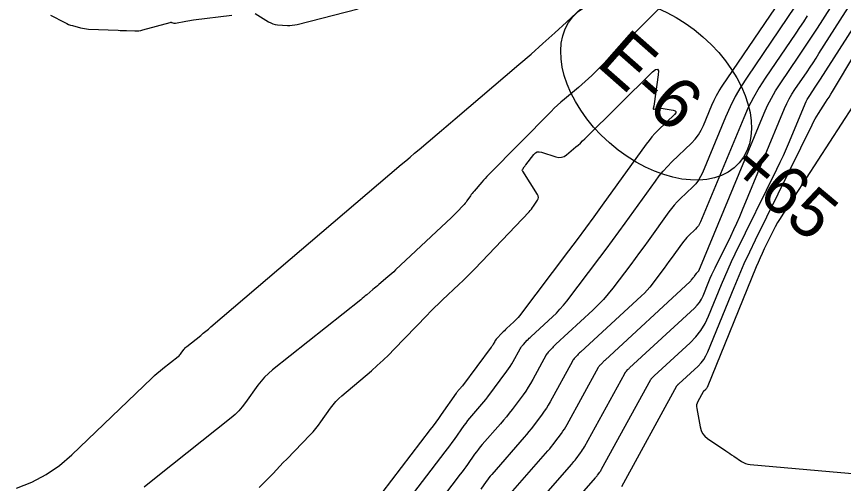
# Model space of a CAD drawing. Extents: x 1005228 to 1008882, y 1883389 to 1885754.
# Drawn here: x 1007760 to 1007862.3, y 1884472.7 to 1884530.4 of the extents above; entities that cross this region are included whole.
import ezdxf

# ---------------------------------------------------------------- set-up
doc = ezdxf.new("R2010")
doc.units = 0
for name, color, linetype in [('C-ANNO-NOTE', 7, 'Continuous'), ('R_Erosion', 7, 'Continuous'), ('S_BASELINE', 7, 'Continuous'), ('S_BRIDGE', 7, 'Continuous')]:
    doc.layers.add(name, color=color, linetype=linetype)

msp = doc.modelspace()

# ---------------------------------------------------------------- linework, layer by layer
at = {"layer": 'C-ANNO-NOTE'}
for points in [[(1007760.01, 1884472.07), (1007761.9, 1884472.81), (1007763.67, 1884473.75), (1007765.33, 1884474.87), (1007766.86, 1884476.2), (1007776.76, 1884485.69), (1007777.08, 1884486), (1007777.42, 1884486.3), (1007777.76, 1884486.59), (1007778.11, 1884486.87), (1007780, 1884488.38), (1007780.1, 1884488.47), (1007780.2, 1884488.56), (1007780.29, 1884488.67), (1007780.37, 1884488.78), (1007780.69, 1884489.22), (1007780.78, 1884489.33), (1007780.87, 1884489.43), (1007780.96, 1884489.53), (1007781.07, 1884489.62), (1007782.78, 1884490.98), (1007783.1, 1884491.24), (1007783.42, 1884491.5), (1007783.73, 1884491.76), (1007784.05, 1884492.03), (1007807.58, 1884512.12), (1007808.14, 1884512.59), (1007808.69, 1884513.06), (1007809.24, 1884513.53), (1007809.8, 1884514), (1007812.02, 1884515.88), (1007812.57, 1884516.35), (1007813.13, 1884516.83), (1007813.68, 1884517.3), (1007814.23, 1884517.77), (1007822.14, 1884524.51), (1007823.63, 1884525.8), (1007825.11, 1884527.11), (1007826.58, 1884528.43), (1007828.03, 1884529.77), (1007845.59, 1884546.16)], [(1007824.7, 1884465.47), (1007831.59, 1884473.36), (1007831.66, 1884473.44), (1007831.73, 1884473.52), (1007831.8, 1884473.61), (1007831.87, 1884473.7), (1007832.13, 1884474.05), (1007832.19, 1884474.13), (1007832.25, 1884474.22), (1007832.31, 1884474.32), (1007832.36, 1884474.41), (1007838.45, 1884485.51), (1007838.47, 1884485.56), (1007838.5, 1884485.6), (1007838.54, 1884485.64), (1007838.57, 1884485.68), (1007838.71, 1884485.83), (1007838.75, 1884485.87), (1007838.78, 1884485.9), (1007838.82, 1884485.94), (1007838.86, 1884485.97), (1007843.31, 1884490.08), (1007844.01, 1884490.81), (1007844.63, 1884491.6), (1007845.16, 1884492.46), (1007845.59, 1884493.38), (1007847.17, 1884497.27), (1007847.58, 1884498.24), (1007847.99, 1884499.19), (1007848.43, 1884500.14), (1007848.88, 1884501.08), (1007854.04, 1884511.56), (1007854.45, 1884512.41), (1007854.84, 1884513.26), (1007855.22, 1884514.12), (1007855.59, 1884514.98), (1007857.52, 1884519.63), (1007857.64, 1884519.91), (1007857.78, 1884520.17), (1007857.93, 1884520.43), (1007858.09, 1884520.69), (1007858.77, 1884521.69), (1007858.94, 1884521.94), (1007859.1, 1884522.19), (1007859.27, 1884522.44), (1007859.43, 1884522.69), (1007868.54, 1884536.99)], [(1007819.94, 1884470.09), (1007825.72, 1884476.7), (1007825.94, 1884476.96), (1007826.16, 1884477.22), (1007826.37, 1884477.49), (1007826.57, 1884477.75), (1007827.38, 1884478.84), (1007827.58, 1884479.11), (1007827.77, 1884479.39), (1007827.94, 1884479.68), (1007828.11, 1884479.97), (1007831.98, 1884487.03), (1007832.03, 1884487.12), (1007832.09, 1884487.2), (1007832.15, 1884487.28), (1007832.22, 1884487.35), (1007832.49, 1884487.64), (1007832.56, 1884487.72), (1007832.63, 1884487.79), (1007832.7, 1884487.86), (1007832.78, 1884487.93), (1007843.29, 1884497.64), (1007843.35, 1884497.69), (1007843.4, 1884497.74), (1007843.44, 1884497.8), (1007843.49, 1884497.85), (1007843.66, 1884498.09), (1007843.71, 1884498.14), (1007843.75, 1884498.2), (1007843.79, 1884498.26), (1007843.84, 1884498.32), (1007844.04, 1884498.6), (1007844.06, 1884498.63), (1007844.09, 1884498.67), (1007844.12, 1884498.7), (1007844.15, 1884498.73), (1007844.27, 1884498.85), (1007844.3, 1884498.88), (1007844.33, 1884498.91), (1007844.35, 1884498.95), (1007844.37, 1884498.99), (1007852.46, 1884518.48), (1007852.88, 1884519.42), (1007853.35, 1884520.35), (1007853.86, 1884521.24), (1007854.42, 1884522.11), (1007856.76, 1884525.55), (1007857.34, 1884526.41), (1007857.91, 1884527.28), (1007858.48, 1884528.14), (1007859.04, 1884529.02), (1007862.55, 1884534.53)], [(1007840.11, 1884532.04), (1007835.26, 1884527.23), (1007834.76, 1884526.75), (1007834.27, 1884526.26), (1007833.78, 1884525.78), (1007833.29, 1884525.29), (1007831.14, 1884523.16), (1007830.73, 1884522.77), (1007830.32, 1884522.39), (1007829.91, 1884522.02), (1007829.48, 1884521.65), (1007827.76, 1884520.22), (1007827.33, 1884519.85), (1007826.92, 1884519.48), (1007826.51, 1884519.09), (1007826.11, 1884518.7), (1007818.36, 1884510.86), (1007818.15, 1884510.64), (1007817.94, 1884510.41), (1007817.74, 1884510.19), (1007817.53, 1884509.96), (1007816.58, 1884508.84), (1007816.46, 1884508.7), (1007816.34, 1884508.55), (1007816.23, 1884508.41), (1007816.13, 1884508.25), (1007815.71, 1884507.64), (1007815.6, 1884507.49), (1007815.49, 1884507.34), (1007815.37, 1884507.2), (1007815.25, 1884507.07), (1007814.48, 1884506.26), (1007814.31, 1884506.08), (1007814.13, 1884505.91), (1007813.96, 1884505.73), (1007813.78, 1884505.56), (1007806.89, 1884499.08), (1007806.65, 1884498.86), (1007806.41, 1884498.65), (1007806.17, 1884498.43), (1007805.92, 1884498.22), (1007804.82, 1884497.28), (1007804.63, 1884497.13), (1007804.44, 1884496.97), (1007804.26, 1884496.81), (1007804.07, 1884496.65), (1007803.33, 1884496.02), (1007803.14, 1884495.86), (1007802.96, 1884495.7), (1007802.77, 1884495.55), (1007802.58, 1884495.4), (1007791.66, 1884486.71), (1007791.16, 1884486.28), (1007790.69, 1884485.83), (1007790.26, 1884485.33), (1007789.86, 1884484.81), (1007788.33, 1884482.66), (1007787.93, 1884482.14), (1007787.5, 1884481.65), (1007787.04, 1884481.19), (1007786.54, 1884480.76), (1007777.47, 1884473.55), (1007775.8, 1884472.19)], [(1007789.53, 1884530.81), (1007791.18, 1884529.8), (1007791.44, 1884529.66), (1007791.72, 1884529.55), (1007792.01, 1884529.48), (1007792.3, 1884529.44), (1007793.51, 1884529.35), (1007793.81, 1884529.35), (1007794.11, 1884529.36), (1007794.41, 1884529.4), (1007794.7, 1884529.46), (1007802.24, 1884531.4)], [(1007807.42, 1884469.23), (1007813.02, 1884476.56), (1007813.31, 1884476.94), (1007813.6, 1884477.32), (1007813.88, 1884477.71), (1007814.15, 1884478.1), (1007815.36, 1884479.82), (1007815.59, 1884480.13), (1007815.82, 1884480.43), (1007816.06, 1884480.73), (1007816.31, 1884481.02), (1007817.31, 1884482.17), (1007817.56, 1884482.46), (1007817.8, 1884482.76), (1007818.04, 1884483.06), (1007818.27, 1884483.36), (1007820.65, 1884486.55), (1007820.86, 1884486.84), (1007821.06, 1884487.13), (1007821.25, 1884487.44), (1007821.42, 1884487.74), (1007822.29, 1884489.32), (1007822.37, 1884489.46), (1007822.47, 1884489.61), (1007822.57, 1884489.74), (1007822.69, 1884489.87), (1007823.16, 1884490.37), (1007823.28, 1884490.49), (1007823.4, 1884490.62), (1007823.53, 1884490.74), (1007823.65, 1884490.85), (1007826.29, 1884493.29), (1007826.76, 1884493.75), (1007827.21, 1884494.22), (1007827.64, 1884494.72), (1007828.05, 1884495.23), (1007832.12, 1884500.61), (1007832.92, 1884501.67), (1007833.71, 1884502.74), (1007834.5, 1884503.81), (1007835.27, 1884504.89), (1007839.01, 1884510.08), (1007839.48, 1884510.71), (1007839.98, 1884511.31), (1007840.5, 1884511.89), (1007841.06, 1884512.45), (1007843.48, 1884514.79), (1007843.93, 1884515.28), (1007844.33, 1884515.81), (1007844.68, 1884516.37), (1007844.96, 1884516.97), (1007846, 1884519.46), (1007846.27, 1884520.08), (1007846.57, 1884520.67), (1007846.91, 1884521.26), (1007847.27, 1884521.82), (1007853.87, 1884531.54)], [(1007856.3, 1884531.71), (1007850.35, 1884522.95), (1007849.59, 1884521.76), (1007848.89, 1884520.53), (1007848.25, 1884519.28), (1007847.67, 1884517.98), (1007844.82, 1884511.12), (1007844.59, 1884510.63), (1007844.32, 1884510.18), (1007844, 1884509.76), (1007843.63, 1884509.37), (1007842.09, 1884507.88), (1007841.71, 1884507.5), (1007841.35, 1884507.1), (1007841.01, 1884506.68), (1007840.68, 1884506.26), (1007838.13, 1884502.7), (1007837.59, 1884501.96), (1007837.06, 1884501.23), (1007836.51, 1884500.5), (1007835.97, 1884499.77), (1007833.74, 1884496.83), (1007833.18, 1884496.11), (1007832.58, 1884495.42), (1007831.95, 1884494.76), (1007831.29, 1884494.12), (1007826.69, 1884489.88), (1007826.59, 1884489.78), (1007826.48, 1884489.67), (1007826.37, 1884489.57), (1007826.27, 1884489.46), (1007825.86, 1884489.03), (1007825.77, 1884488.92), (1007825.68, 1884488.8), (1007825.59, 1884488.68), (1007825.52, 1884488.56), (1007823.86, 1884485.54), (1007823.58, 1884485.04), (1007823.28, 1884484.56), (1007822.97, 1884484.09), (1007822.64, 1884483.63), (1007821.28, 1884481.81), (1007820.93, 1884481.36), (1007820.58, 1884480.92), (1007820.22, 1884480.48), (1007819.85, 1884480.05), (1007817.6, 1884477.47), (1007817.36, 1884477.18), (1007817.12, 1884476.89), (1007816.88, 1884476.58), (1007816.66, 1884476.27), (1007815.78, 1884475.02), (1007815.56, 1884474.71), (1007815.34, 1884474.4), (1007815.11, 1884474.09), (1007814.88, 1884473.79), (1007810.86, 1884468.52)], [(1007764.22, 1884530.63), (1007765.98, 1884529.69), (1007766.21, 1884529.58), (1007766.45, 1884529.48), (1007766.69, 1884529.39), (1007766.93, 1884529.32), (1007767.91, 1884529.05), (1007768.16, 1884528.99), (1007768.41, 1884528.95), (1007768.66, 1884528.91), (1007768.92, 1884528.9), (1007772.56, 1884528.74), (1007772.82, 1884528.73), (1007773.07, 1884528.72), (1007773.33, 1884528.71), (1007773.59, 1884528.7), (1007774.62, 1884528.67), (1007774.88, 1884528.67), (1007775.13, 1884528.69), (1007775.38, 1884528.73), (1007775.63, 1884528.79), (1007779.01, 1884529.72), (1007779.07, 1884529.73), (1007779.12, 1884529.73), (1007779.18, 1884529.72), (1007779.23, 1884529.71), (1007779.45, 1884529.64), (1007779.51, 1884529.62), (1007779.57, 1884529.62), (1007779.62, 1884529.62), (1007779.68, 1884529.62), (1007780.96, 1884529.88), (1007781.19, 1884529.93), (1007781.43, 1884529.97), (1007781.66, 1884530.01), (1007781.9, 1884530.04), (1007786.63, 1884530.63)], [(1007857.79, 1884530.54), (1007857.32, 1884529.81), (1007856.84, 1884529.09), (1007856.36, 1884528.38), (1007852.59, 1884522.83), (1007851.83, 1884521.65), (1007851.13, 1884520.43), (1007850.5, 1884519.18), (1007849.93, 1884517.9), (1007844.59, 1884505.05), (1007844.47, 1884504.79), (1007844.32, 1884504.55), (1007844.15, 1884504.32), (1007843.95, 1884504.11), (1007843.12, 1884503.3), (1007842.91, 1884503.1), (1007842.72, 1884502.88), (1007842.54, 1884502.66), (1007842.36, 1884502.43), (1007840.98, 1884500.51), (1007840.69, 1884500.11), (1007840.4, 1884499.72), (1007840.11, 1884499.32), (1007839.82, 1884498.93), (1007838.62, 1884497.34), (1007838.31, 1884496.96), (1007837.99, 1884496.58), (1007837.65, 1884496.22), (1007837.29, 1884495.88), (1007829.74, 1884488.9), (1007829.64, 1884488.82), (1007829.56, 1884488.73), (1007829.47, 1884488.64), (1007829.38, 1884488.55), (1007829.04, 1884488.19), (1007828.96, 1884488.1), (1007828.88, 1884488), (1007828.81, 1884487.9), (1007828.75, 1884487.79), (1007825.99, 1884482.75), (1007825.76, 1884482.36), (1007825.53, 1884481.98), (1007825.27, 1884481.6), (1007825.01, 1884481.23), (1007823.92, 1884479.78), (1007823.65, 1884479.42), (1007823.37, 1884479.07), (1007823.08, 1884478.72), (1007822.79, 1884478.38), (1007818.77, 1884473.78), (1007818.59, 1884473.56), (1007818.41, 1884473.34), (1007818.24, 1884473.11), (1007818.07, 1884472.88), (1007817.41, 1884471.94)], [(1007834.85, 1884472.29), (1007841.68, 1884484.75), (1007841.7, 1884484.77), (1007841.71, 1884484.8), (1007841.73, 1884484.82), (1007841.75, 1884484.84), (1007841.82, 1884484.92), (1007841.84, 1884484.94), (1007841.86, 1884484.96), (1007841.88, 1884484.98), (1007841.9, 1884485), (1007844.28, 1884487.19), (1007844.65, 1884487.58), (1007844.98, 1884488), (1007845.26, 1884488.46), (1007845.5, 1884488.95), (1007848.73, 1884496.91), (1007849.35, 1884498.4), (1007850, 1884499.87), (1007850.67, 1884501.34), (1007851.37, 1884502.79), (1007858.39, 1884517.06), (1007858.57, 1884517.42), (1007858.77, 1884517.77), (1007858.97, 1884518.12), (1007859.18, 1884518.46), (1007860.05, 1884519.8), (1007860.27, 1884520.14), (1007860.49, 1884520.48), (1007860.7, 1884520.82), (1007860.9, 1884521.17), (1007863.8, 1884525.98)], [(1007863.41, 1884519.36), (1007854.75, 1884505.98), (1007854.42, 1884505.46), (1007854.12, 1884504.94), (1007853.82, 1884504.4), (1007853.55, 1884503.86), (1007852.47, 1884501.68), (1007852.21, 1884501.13), (1007851.96, 1884500.58), (1007851.71, 1884500.02), (1007851.48, 1884499.46), (1007845.4, 1884484.53), (1007845.37, 1884484.47), (1007845.34, 1884484.41), (1007845.29, 1884484.35), (1007845.25, 1884484.3), (1007844.94, 1884484.02), (1007844.93, 1884484.01), (1007844.92, 1884484), (1007844.92, 1884484), (1007844.91, 1884483.99), (1007844.26, 1884482.79), (1007844.16, 1884482.59), (1007844.11, 1884482.38), (1007844.1, 1884482.16), (1007844.12, 1884481.94), (1007844.53, 1884479.65), (1007844.65, 1884479.22), (1007844.85, 1884478.84), (1007845.12, 1884478.5), (1007845.46, 1884478.22), (1007847.71, 1884476.7), (1007847.96, 1884476.53), (1007848.2, 1884476.37), (1007848.44, 1884476.2), (1007848.69, 1884476.04), (1007849.66, 1884475.38), (1007849.91, 1884475.23), (1007850.17, 1884475.12), (1007850.45, 1884475.04), (1007850.74, 1884474.99), (1007872.7, 1884473.08)]]:
    msp.add_lwpolyline(points, dxfattribs=at)
at = {"layer": 'R_Erosion'}
msp.add_ellipse((1007839.1, 1884521.38), major_axis=(10.28, -9.05), ratio=0.638788, dxfattribs=at)
at = {"layer": 'S_BRIDGE'}
for points in [[(1007821.12, 1884466.4), (1007828.66, 1884475.03), (1007828.8, 1884475.2), (1007828.94, 1884475.37), (1007829.08, 1884475.55), (1007829.22, 1884475.72), (1007829.75, 1884476.44), (1007829.89, 1884476.62), (1007830.01, 1884476.81), (1007830.13, 1884477), (1007830.24, 1884477.19), (1007835.22, 1884486.27), (1007835.25, 1884486.34), (1007835.3, 1884486.4), (1007835.34, 1884486.46), (1007835.39, 1884486.52), (1007835.6, 1884486.74), (1007835.65, 1884486.79), (1007835.71, 1884486.84), (1007835.76, 1884486.9), (1007835.82, 1884486.95), (1007843.85, 1884494.37), (1007844.18, 1884494.71), (1007844.46, 1884495.07), (1007844.7, 1884495.46), (1007844.9, 1884495.89), (1007845.62, 1884497.64), (1007845.8, 1884498.07), (1007845.99, 1884498.51), (1007846.18, 1884498.94), (1007846.39, 1884499.36), (1007848.32, 1884503.28), (1007848.7, 1884504.08), (1007849.08, 1884504.89), (1007849.43, 1884505.7), (1007849.78, 1884506.51), (1007854.99, 1884519.05), (1007855.26, 1884519.67), (1007855.56, 1884520.26), (1007855.89, 1884520.84), (1007856.26, 1884521.4), (1007857.76, 1884523.62), (1007858.14, 1884524.17), (1007858.51, 1884524.73), (1007858.87, 1884525.29), (1007859.23, 1884525.86), (1007865.54, 1884535.76)], [(1007790.02, 1884472.14), (1007791.73, 1884473.9), (1007792.15, 1884474.35), (1007792.58, 1884474.79), (1007793, 1884475.23), (1007793.43, 1884475.67), (1007796.33, 1884478.67), (1007796.68, 1884479.05), (1007797.02, 1884479.44), (1007797.35, 1884479.85), (1007797.65, 1884480.27), (1007798.85, 1884481.98), (1007799.16, 1884482.39), (1007799.5, 1884482.78), (1007799.86, 1884483.15), (1007800.24, 1884483.5), (1007803.89, 1884486.61), (1007804.62, 1884487.24), (1007805.33, 1884487.9), (1007806.03, 1884488.57), (1007806.71, 1884489.26), (1007810.73, 1884493.44), (1007811.21, 1884493.93), (1007811.7, 1884494.42), (1007812.2, 1884494.9), (1007812.7, 1884495.38), (1007814.71, 1884497.28), (1007815.22, 1884497.76), (1007815.71, 1884498.24), (1007816.2, 1884498.73), (1007816.68, 1884499.23), (1007823.39, 1884506.29), (1007823.54, 1884506.45), (1007823.68, 1884506.62), (1007823.81, 1884506.79), (1007823.94, 1884506.97), (1007824.43, 1884507.7), (1007824.52, 1884507.88), (1007824.55, 1884508.06), (1007824.53, 1884508.24), (1007824.44, 1884508.42), (1007822.6, 1884511.29), (1007822.56, 1884511.36), (1007822.55, 1884511.43), (1007822.57, 1884511.5), (1007822.6, 1884511.57), (1007822.8, 1884511.84), (1007822.85, 1884511.91), (1007822.9, 1884511.98), (1007822.95, 1884512.05), (1007823, 1884512.11), (1007823.99, 1884513.39), (1007824.19, 1884513.58), (1007824.41, 1884513.69), (1007824.65, 1884513.72), (1007824.92, 1884513.67), (1007826.71, 1884513.08), (1007827.06, 1884513.01), (1007827.39, 1884513.03), (1007827.71, 1884513.13), (1007828.01, 1884513.33), (1007829.17, 1884514.3), (1007829.45, 1884514.54), (1007829.74, 1884514.79), (1007830.01, 1884515.05), (1007830.28, 1884515.31), (1007838.65, 1884523.59), (1007839.02, 1884523.89), (1007839.27, 1884523.94), (1007839.38, 1884523.71), (1007839.36, 1884523.23), (1007838.86, 1884519.65), (1007838.85, 1884519.58), (1007838.84, 1884519.51), (1007838.82, 1884519.43), (1007838.81, 1884519.36), (1007838.75, 1884519.08), (1007838.75, 1884519.02), (1007838.77, 1884518.98), (1007838.8, 1884518.97), (1007838.86, 1884518.99), (1007839.17, 1884519.11), (1007839.25, 1884519.14), (1007839.32, 1884519.15), (1007839.4, 1884519.15), (1007839.48, 1884519.15), (1007841.19, 1884518.86), (1007841.44, 1884518.79), (1007841.55, 1884518.68), (1007841.52, 1884518.52), (1007841.36, 1884518.32), (1007839.36, 1884516.38), (1007838.96, 1884515.98), (1007838.58, 1884515.56), (1007838.22, 1884515.12), (1007837.87, 1884514.66), (1007832.42, 1884507.08), (1007831.4, 1884505.66), (1007830.36, 1884504.25), (1007829.32, 1884502.85), (1007828.27, 1884501.45), (1007822.19, 1884493.42), (1007822.03, 1884493.21), (1007821.86, 1884493.01), (1007821.68, 1884492.82), (1007821.49, 1884492.64), (1007820.61, 1884491.83), (1007820.47, 1884491.7), (1007820.33, 1884491.56), (1007820.19, 1884491.42), (1007820.05, 1884491.28), (1007819.38, 1884490.57), (1007819.32, 1884490.5), (1007819.25, 1884490.41), (1007819.19, 1884490.33), (1007819.14, 1884490.24), (1007818.94, 1884489.88), (1007818.89, 1884489.79), (1007818.84, 1884489.7), (1007818.78, 1884489.62), (1007818.72, 1884489.54), (1007815.15, 1884484.75), (1007815.09, 1884484.67), (1007815.03, 1884484.6), (1007814.96, 1884484.52), (1007814.9, 1884484.44), (1007814.64, 1884484.15), (1007814.57, 1884484.07), (1007814.51, 1884483.99), (1007814.45, 1884483.91), (1007814.39, 1884483.83), (1007812.53, 1884481.18), (1007812.2, 1884480.71), (1007811.86, 1884480.25), (1007811.52, 1884479.79), (1007811.17, 1884479.33), (1007803.99, 1884469.93)]]:
    msp.add_lwpolyline(points, dxfattribs=at)

# ---------------------------------------------------------------- texts
at = {"layer": 'R_Erosion'}
msp.add_text('E-6', height=6.25, rotation=318.6338, dxfattribs=at).set_placement((1007831.52, 1884524.51))
at = {"layer": 'S_BASELINE'}
msp.add_text('+65', height=6, rotation=320, dxfattribs=at).set_placement((1007847.86, 1884511.11))

doc.saveas('drawing.dxf')
